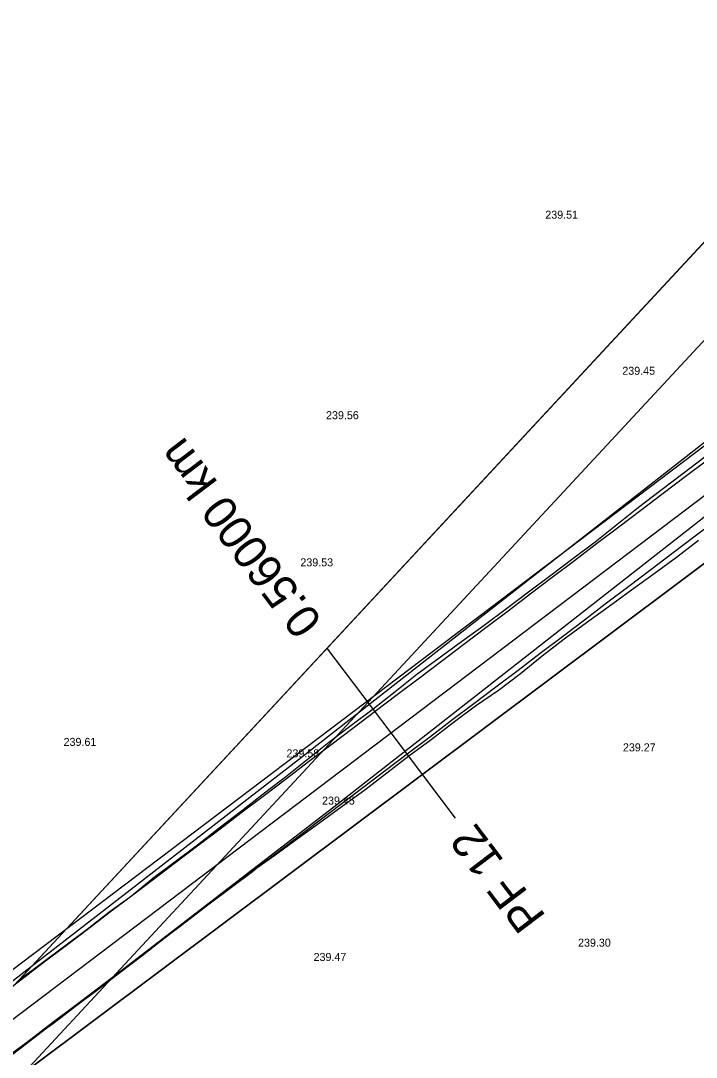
# Model space of a CAD drawing. Extents: x -555887 to -552101, y -1100251 to -1096546.
# Drawn here: x -555215.6 to -555164.9, y -1098573.8 to -1098496.1 of the extents above; entities that cross this region are included whole.
import ezdxf

# ---------------------------------------------------------------- set-up
doc = ezdxf.new("R2010")
doc.units = 0
for name, color, linetype in [('PARCELY_cesty', 7, 'Continuous'), ('POLYGONY_SITUACE_PF', 7, 'Continuous'), ('POLYGONY_SITUACE_PF_POPISY', 7, 'Continuous'), ('POLYGONY_SITUACE_PO', 7, 'Continuous'), ('ram_VC1', 7, 'Continuous'), ('Výškopis', 7, 'Continuous'), ('ZSST', 7, 'Continuous'), ('zájem', 7, 'Continuous')]:
    doc.layers.add(name, color=color, linetype=linetype)

msp = doc.modelspace()

# ---------------------------------------------------------------- linework, layer by layer
at = {"layer": 'PARCELY_cesty'}
msp.add_lwpolyline([(-555432.8, -1098748.4), (-555400.008, -1098712.208), (-555389.921, -1098701.565), (-555373.936, -1098686.469), (-555357.132, -1098672.276), (-555340.17, -1098659.659), (-555299.833, -1098630.198), (-555259.851, -1098600.294), (-555132.603, -1098503.989), (-555074.98, -1098461.38), (-555070.799, -1098455.669), (-555054.379, -1098443.798), (-555047.89, -1098441.68), (-555024.771, -1098425.173), (-554988.252, -1098399.708), (-554740.35, -1098228.23), (-554737.92, -1098224.21)], dxfattribs=at)
at = {"layer": 'POLYGONY_SITUACE_PF'}
for p, q in [((-555187.802, -1098549.528), (-555192.63, -1098543.148)), ((-555182.974, -1098555.907), (-555187.802, -1098549.528))]:
    msp.add_line(p, q, dxfattribs=at)
at = {"layer": 'POLYGONY_SITUACE_PO'}
for p, q in [((-555130.806, -1098506.391), (-555258.048, -1098602.691)), ((-555164.267, -1098528.842), (-555165.928, -1098530.099)), ((-555164.091, -1098529.074), (-555165.752, -1098530.331)), ((-555164.091, -1098529.074), (-555165.752, -1098530.331)), ((-555165.928, -1098530.099), (-555167.581, -1098531.367)), ((-555165.752, -1098530.331), (-555167.414, -1098531.589)), ((-555165.752, -1098530.331), (-555167.414, -1098531.589)), ((-555167.581, -1098531.367), (-555169.246, -1098532.62)), ((-555167.414, -1098531.589), (-555169.075, -1098532.846)), ((-555167.414, -1098531.589), (-555169.075, -1098532.846)), ((-555169.246, -1098532.62), (-555170.876, -1098533.918)), ((-555169.075, -1098532.846), (-555170.736, -1098534.103)), ((-555169.075, -1098532.846), (-555170.736, -1098534.103)), ((-555163.338, -1098533.521), (-555165, -1098534.778)), ((-555163.338, -1098533.521), (-555165, -1098534.778)), ((-555170.876, -1098533.918), (-555172.507, -1098535.216)), ((-555170.736, -1098534.103), (-555172.397, -1098535.36)), ((-555170.736, -1098534.103), (-555172.397, -1098535.36)), ((-555172.507, -1098535.216), (-555174.168, -1098536.472)), ((-555165, -1098534.778), (-555166.661, -1098536.035)), ((-555165, -1098534.778), (-555166.661, -1098536.035)), ((-555164.751, -1098535.107), (-555166.402, -1098536.377)), ((-555172.397, -1098535.36), (-555174.058, -1098536.618)), ((-555172.397, -1098535.36), (-555174.058, -1098536.618)), ((-555166.661, -1098536.035), (-555168.322, -1098537.293)), ((-555166.661, -1098536.035), (-555168.322, -1098537.293)), ((-555174.168, -1098536.472), (-555175.83, -1098537.729)), ((-555174.058, -1098536.618), (-555175.72, -1098537.875)), ((-555174.058, -1098536.618), (-555175.72, -1098537.875)), ((-555166.402, -1098536.377), (-555168.088, -1098537.602)), ((-555168.322, -1098537.293), (-555169.983, -1098538.55)), ((-555168.322, -1098537.293), (-555169.983, -1098538.55)), ((-555175.83, -1098537.729), (-555177.5, -1098538.975)), ((-555175.72, -1098537.875), (-555177.381, -1098539.132)), ((-555175.72, -1098537.875), (-555177.381, -1098539.132)), ((-555168.088, -1098537.602), (-555169.781, -1098538.818)), ((-555177.5, -1098538.975), (-555179.159, -1098540.235)), ((-555177.381, -1098539.132), (-555179.042, -1098540.389)), ((-555177.381, -1098539.132), (-555179.042, -1098540.389)), ((-555169.983, -1098538.55), (-555171.644, -1098539.807)), ((-555169.983, -1098538.55), (-555171.644, -1098539.807)), ((-555169.781, -1098538.818), (-555171.466, -1098540.042)), ((-555171.644, -1098539.807), (-555173.306, -1098541.064)), ((-555171.644, -1098539.807), (-555173.306, -1098541.064)), ((-555179.159, -1098540.235), (-555180.839, -1098541.466)), ((-555179.042, -1098540.389), (-555180.703, -1098541.647)), ((-555179.042, -1098540.389), (-555180.703, -1098541.647)), ((-555171.466, -1098540.042), (-555173.151, -1098541.268)), ((-555180.839, -1098541.466), (-555182.523, -1098542.694)), ((-555173.306, -1098541.064), (-555174.967, -1098542.322)), ((-555173.306, -1098541.064), (-555174.967, -1098542.322)), ((-555173.151, -1098541.268), (-555174.83, -1098542.503)), ((-555180.703, -1098541.647), (-555182.364, -1098542.904)), ((-555180.703, -1098541.647), (-555182.364, -1098542.904)), ((-555182.523, -1098542.694), (-555184.205, -1098543.923)), ((-555182.364, -1098542.904), (-555184.026, -1098544.161)), ((-555182.364, -1098542.904), (-555184.026, -1098544.161)), ((-555174.967, -1098542.322), (-555176.628, -1098543.579)), ((-555174.967, -1098542.322), (-555176.628, -1098543.579)), ((-555174.83, -1098542.503), (-555176.474, -1098543.782)), ((-555176.628, -1098543.579), (-555178.289, -1098544.836)), ((-555176.628, -1098543.579), (-555178.289, -1098544.836)), ((-555176.474, -1098543.782), (-555178.101, -1098545.085)), ((-555184.205, -1098543.923), (-555185.886, -1098545.155)), ((-555184.026, -1098544.161), (-555185.687, -1098545.418)), ((-555184.026, -1098544.161), (-555185.687, -1098545.418)), ((-555185.886, -1098545.155), (-555187.517, -1098546.452)), ((-555178.289, -1098544.836), (-555179.95, -1098546.093)), ((-555178.289, -1098544.836), (-555179.95, -1098546.093)), ((-555178.101, -1098545.085), (-555179.765, -1098546.338)), ((-555185.687, -1098545.418), (-555187.348, -1098546.676)), ((-555185.687, -1098545.418), (-555187.348, -1098546.676)), ((-555179.95, -1098546.093), (-555181.612, -1098547.351)), ((-555179.95, -1098546.093), (-555181.612, -1098547.351)), ((-555187.517, -1098546.452), (-555189.155, -1098547.74)), ((-555187.348, -1098546.676), (-555189.009, -1098547.933)), ((-555187.348, -1098546.676), (-555189.009, -1098547.933)), ((-555179.765, -1098546.338), (-555181.482, -1098547.522)), ((-555181.612, -1098547.351), (-555183.273, -1098548.608)), ((-555181.612, -1098547.351), (-555183.273, -1098548.608)), ((-555181.482, -1098547.522), (-555183.156, -1098548.762)), ((-555189.155, -1098547.74), (-555190.819, -1098548.994)), ((-555189.009, -1098547.933), (-555190.67, -1098549.19)), ((-555189.009, -1098547.933), (-555190.67, -1098549.19)), ((-555190.819, -1098548.994), (-555192.483, -1098550.248)), ((-555190.67, -1098549.19), (-555192.332, -1098550.447)), ((-555190.67, -1098549.19), (-555192.332, -1098550.447)), ((-555183.273, -1098548.608), (-555184.934, -1098549.865)), ((-555183.273, -1098548.608), (-555184.934, -1098549.865)), ((-555183.156, -1098548.762), (-555184.798, -1098550.044)), ((-555184.934, -1098549.865), (-555186.595, -1098551.122)), ((-555184.934, -1098549.865), (-555186.595, -1098551.122)), ((-555192.483, -1098550.248), (-555194.108, -1098551.552)), ((-555192.332, -1098550.447), (-555193.993, -1098551.705)), ((-555192.332, -1098550.447), (-555193.993, -1098551.705)), ((-555184.798, -1098550.044), (-555186.475, -1098551.281)), ((-555194.108, -1098551.552), (-555195.739, -1098552.849)), ((-555186.595, -1098551.122), (-555188.256, -1098552.38)), ((-555186.595, -1098551.122), (-555188.256, -1098552.38)), ((-555186.475, -1098551.281), (-555188.14, -1098552.533)), ((-555193.993, -1098551.705), (-555195.654, -1098552.962)), ((-555193.993, -1098551.705), (-555195.654, -1098552.962)), ((-555195.739, -1098552.849), (-555197.4, -1098554.107)), ((-555195.654, -1098552.962), (-555197.315, -1098554.219)), ((-555195.654, -1098552.962), (-555197.315, -1098554.219)), ((-555188.256, -1098552.38), (-555189.918, -1098553.637)), ((-555188.256, -1098552.38), (-555189.918, -1098553.637)), ((-555188.14, -1098552.533), (-555189.78, -1098553.818)), ((-555189.918, -1098553.637), (-555191.579, -1098554.894)), ((-555189.918, -1098553.637), (-555191.579, -1098554.894)), ((-555189.78, -1098553.818), (-555191.474, -1098555.033)), ((-555197.4, -1098554.107), (-555199.037, -1098555.396)), ((-555197.315, -1098554.219), (-555198.976, -1098555.476)), ((-555197.315, -1098554.219), (-555198.976, -1098555.476)), ((-555199.037, -1098555.396), (-555200.693, -1098556.661)), ((-555191.579, -1098554.894), (-555193.24, -1098556.151)), ((-555191.579, -1098554.894), (-555193.24, -1098556.151)), ((-555191.474, -1098555.033), (-555193.157, -1098556.261)), ((-555198.976, -1098555.476), (-555200.638, -1098556.734)), ((-555198.976, -1098555.476), (-555200.638, -1098556.734)), ((-555193.24, -1098556.151), (-555194.901, -1098557.409)), ((-555193.24, -1098556.151), (-555194.901, -1098557.409)), ((-555200.693, -1098556.661), (-555202.334, -1098557.944)), ((-555200.638, -1098556.734), (-555202.299, -1098557.991)), ((-555200.638, -1098556.734), (-555202.299, -1098557.991)), ((-555193.157, -1098556.261), (-555194.843, -1098557.485)), ((-555194.901, -1098557.409), (-555196.563, -1098558.666)), ((-555194.901, -1098557.409), (-555196.563, -1098558.666)), ((-555194.843, -1098557.485), (-555196.519, -1098558.724)), ((-555202.334, -1098557.944), (-555204.002, -1098559.192)), ((-555202.299, -1098557.991), (-555203.96, -1098559.248)), ((-555202.299, -1098557.991), (-555203.96, -1098559.248)), ((-555204.002, -1098559.192), (-555205.676, -1098560.433)), ((-555203.96, -1098559.248), (-555205.621, -1098560.505)), ((-555203.96, -1098559.248), (-555205.621, -1098560.505)), ((-555196.563, -1098558.666), (-555198.224, -1098559.923)), ((-555196.563, -1098558.666), (-555198.224, -1098559.923)), ((-555196.519, -1098558.724), (-555197.887, -1098559.668)), ((-555198.224, -1098559.923), (-555199.885, -1098561.18)), ((-555198.224, -1098559.923), (-555199.885, -1098561.18)), ((-555198.213, -1098559.938), (-555199.879, -1098561.188)), ((-555197.887, -1098559.668), (-555198.213, -1098559.938)), ((-555205.676, -1098560.433), (-555207.289, -1098561.753)), ((-555205.621, -1098560.505), (-555207.282, -1098561.763)), ((-555205.621, -1098560.505), (-555207.282, -1098561.763)), ((-555199.885, -1098561.18), (-555201.546, -1098562.438)), ((-555199.885, -1098561.18), (-555201.546, -1098562.438)), ((-555199.879, -1098561.188), (-555201.543, -1098562.441)), ((-555207.289, -1098561.753), (-555208.968, -1098562.988)), ((-555207.282, -1098561.763), (-555208.944, -1098563.02)), ((-555207.282, -1098561.763), (-555208.944, -1098563.02)), ((-555201.546, -1098562.438), (-555203.207, -1098563.695)), ((-555201.546, -1098562.438), (-555203.207, -1098563.695)), ((-555201.543, -1098562.441), (-555203.201, -1098563.704)), ((-555208.968, -1098562.988), (-555210.616, -1098564.263)), ((-555208.944, -1098563.02), (-555210.605, -1098564.277)), ((-555208.944, -1098563.02), (-555210.605, -1098564.277)), ((-555203.207, -1098563.695), (-555204.869, -1098564.952)), ((-555203.207, -1098563.695), (-555204.869, -1098564.952)), ((-555203.201, -1098563.704), (-555204.856, -1098564.968)), ((-555210.616, -1098564.263), (-555212.278, -1098565.519)), ((-555210.605, -1098564.277), (-555212.266, -1098565.534)), ((-555210.605, -1098564.277), (-555212.266, -1098565.534)), ((-555212.278, -1098565.519), (-555213.947, -1098566.766)), ((-555212.266, -1098565.534), (-555213.927, -1098566.792)), ((-555212.266, -1098565.534), (-555213.927, -1098566.792)), ((-555204.869, -1098564.952), (-555206.53, -1098566.209)), ((-555204.869, -1098564.952), (-555206.53, -1098566.209)), ((-555204.856, -1098564.968), (-555206.495, -1098566.256)), ((-555206.53, -1098566.209), (-555208.191, -1098567.467)), ((-555206.53, -1098566.209), (-555208.191, -1098567.467)), ((-555206.495, -1098566.256), (-555208.153, -1098567.517)), ((-555213.947, -1098566.766), (-555215.621, -1098568.006)), ((-555213.927, -1098566.792), (-555215.588, -1098568.049)), ((-555213.927, -1098566.792), (-555215.588, -1098568.049)), ((-555208.191, -1098567.467), (-555209.852, -1098568.724)), ((-555208.191, -1098567.467), (-555209.852, -1098568.724)), ((-555208.153, -1098567.517), (-555209.813, -1098568.776)), ((-555215.588, -1098568.049), (-555217.25, -1098569.306)), ((-555215.588, -1098568.049), (-555217.25, -1098569.306)), ((-555209.852, -1098568.724), (-555211.513, -1098569.981)), ((-555209.852, -1098568.724), (-555211.513, -1098569.981)), ((-555209.813, -1098568.776), (-555211.471, -1098570.037)), ((-555211.513, -1098569.981), (-555213.175, -1098571.238)), ((-555211.513, -1098569.981), (-555213.175, -1098571.238)), ((-555211.471, -1098570.037), (-555213.129, -1098571.299)), ((-555213.175, -1098571.238), (-555214.836, -1098572.496)), ((-555213.175, -1098571.238), (-555214.836, -1098572.496)), ((-555213.129, -1098571.299), (-555214.818, -1098572.519)), ((-555214.836, -1098572.496), (-555216.497, -1098573.753)), ((-555214.836, -1098572.496), (-555216.497, -1098573.753)), ((-555214.818, -1098572.519), (-555216.476, -1098573.781))]:
    msp.add_line(p, q, dxfattribs=at)
at = {"layer": 'ram_VC1'}
for points in [[(-554540.883, -1097849.107), (-554911.618, -1097504.634), (-555880.616, -1098547.506), (-555509.881, -1098891.979)], [(-554547.95, -1097849.366), (-554911.358, -1097511.7), (-555873.55, -1098547.246), (-555510.141, -1098884.912)]]:
    msp.add_lwpolyline(points, close=True, dxfattribs=at)
for points in [[(-554540.883, -1097849.107), (-554911.618, -1097504.634), (-555880.616, -1098547.506), (-555509.881, -1098891.979), (-554540.883, -1097849.107)], [(-555510.141, -1098884.912), (-555873.55, -1098547.246), (-554911.358, -1097511.7), (-554547.95, -1097849.366), (-555510.141, -1098884.912)]]:
    msp.add_lwpolyline(points, dxfattribs=at)
at = {"layer": 'ZSST'}
for points in [[(-555047.93, -1098442.03), (-555072.12, -1098458.86), (-555088.34, -1098470.57), (-555126.84, -1098498.87), (-555144.37, -1098512.2), (-555194.54, -1098551.36), (-555231.55, -1098580.01), (-555250.25, -1098594.37), (-555270.85, -1098609.63), (-555289.58, -1098622.71), (-555305.43, -1098634.04), (-555318.12, -1098644.14), (-555342.33, -1098664.59), (-555361.73, -1098681.61), (-555377.43, -1098695.41), (-555388.84, -1098705.7), (-555402.21, -1098718.08), (-555414.99, -1098731.34), (-555426.44, -1098743.28)], [(-555287.5, -1098626.12), (-555268.65, -1098612.98), (-555247.53, -1098597.58), (-555228.97, -1098583.42), (-555191.88, -1098554.9), (-555141.33, -1098515.33), (-555124.36, -1098502.55), (-555085.58, -1098473.69), (-555070.52, -1098462.55), (-555045.15, -1098444.71)]]:
    msp.add_lwpolyline(points, dxfattribs=at)
at = {"layer": 'zájem'}
for points in [[(-555456.8, -1098789.9), (-555379.7, -1098701.24), (-555376.22, -1098697.48), (-555369.9, -1098690.59), (-555369.08, -1098690.01), (-555302.67, -1098640.32), (-555268.63, -1098614.85), (-555156.39, -1098530.87), (-555094.92, -1098484.89), (-555072.69, -1098467.65), (-555057.79, -1098455.7), (-554947.91, -1098379.76)], [(-554947.91, -1098379.76), (-555057.79, -1098455.7), (-555072.69, -1098467.65), (-555094.92, -1098484.89), (-555156.39, -1098530.87), (-555268.63, -1098614.85), (-555302.67, -1098640.32), (-555369.08, -1098690.01), (-555369.9, -1098690.59), (-555376.22, -1098697.48), (-555379.7, -1098701.24), (-555456.8, -1098789.9)]]:
    msp.add_lwpolyline(points, dxfattribs=at)

# ---------------------------------------------------------------- texts
at = {"layer": 'POLYGONY_SITUACE_PF_POPISY'}
for s, p in [('0.56000 km', (-555192.891, -1098541.147)), ('PF 12', (-555176.142, -1098563.277))]:
    msp.add_text(s, height=2.5, rotation=127.11955, dxfattribs=at).set_placement(p)
at = {"layer": 'Výškopis'}
for s, p in [('239.51', (-555176.246, -1098510.98)), ('239.45', (-555170.468, -1098522.68)), ('239.56', (-555192.688, -1098526.01)), ('239.53', (-555194.614, -1098537.04)), ('239.61', (-555212.372, -1098550.5)), ('239.58', (-555195.654, -1098551.36)), ('239.27', (-555170.424, -1098550.91)), ('239.45', (-555192.988, -1098554.9)), ('239.30', (-555173.788, -1098565.55)), ('239.47', (-555193.623, -1098566.62))]:
    msp.add_text(s, height=0.6, dxfattribs=at).set_placement(p)

doc.saveas('drawing.dxf')
